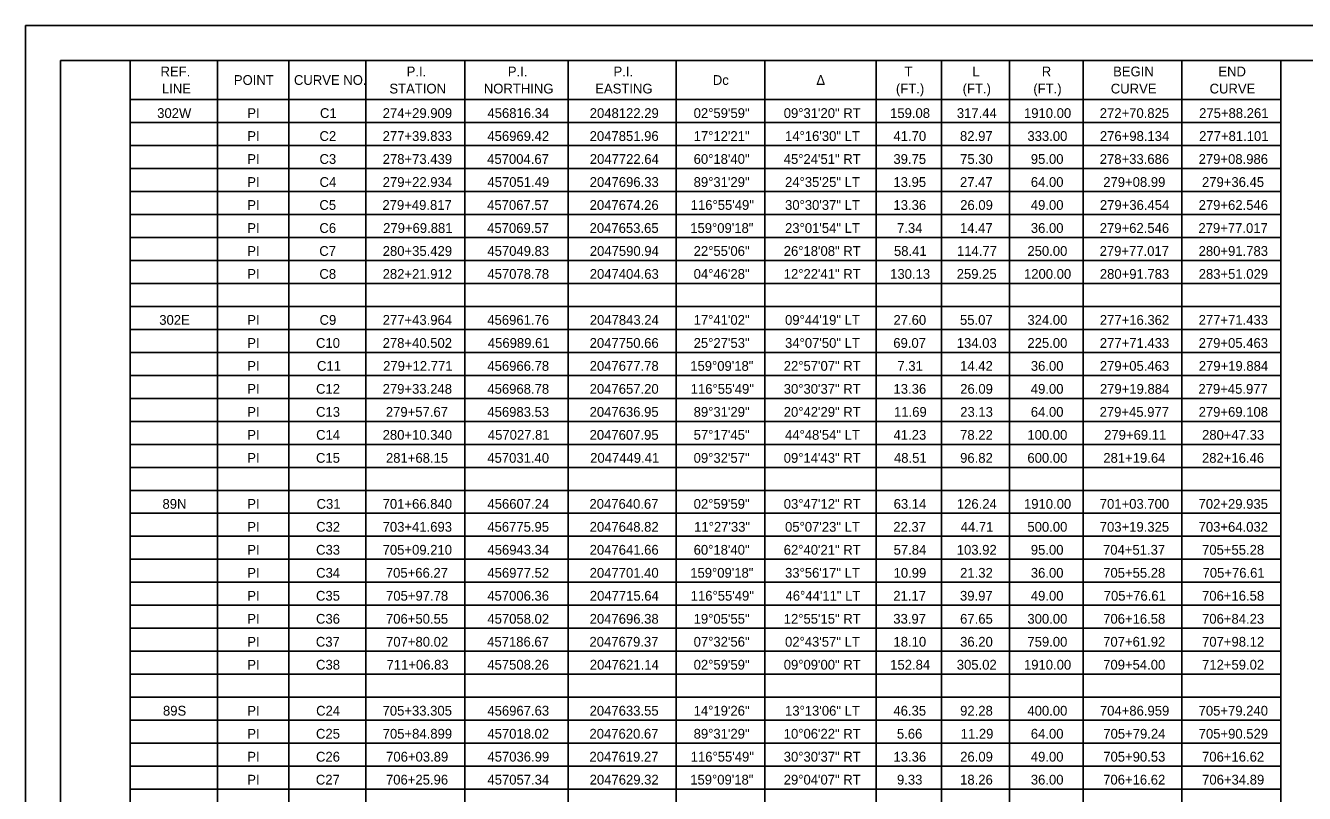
# Model space of a CAD drawing. Extents: x 0 to 34, y 0 to 22.
# Drawn here: x 0 to 18.33, y 11 to 22 of the extents above; entities that cross this region are included whole.
import ezdxf

# ---------------------------------------------------------------- set-up
doc = ezdxf.new("R2010")
doc.units = 0
for name, color, linetype in [('Default', 7, 'Continuous'), ('SH_Border', 7, 'Continuous'), ('SH_Cut_Line', 7, 'Continuous')]:
    doc.layers.add(name, color=color, linetype=linetype)

msp = doc.modelspace()

# ---------------------------------------------------------------- linework, layer by layer
at = {"layer": 'Default'}
for p, q in [((1.5, 21.5), (17.987, 21.5)), ((1.5, 21.5), (1.5, 3.152)), ((2.752, 21.5), (2.752, 3.152)), ((3.773, 21.5), (3.773, 3.152)), ((4.876, 21.5), (4.876, 3.152)), ((6.293, 21.5), (6.293, 3.152)), ((7.775, 21.5), (7.775, 3.152)), ((9.324, 21.5), (9.324, 3.152)), ((10.592, 21.5), (10.592, 3.152)), ((12.189, 21.5), (12.189, 3.152)), ((13.128, 21.5), (13.128, 3.152)), ((14.1, 21.5), (14.1, 3.152)), ((15.154, 21.5), (15.154, 3.152)), ((16.571, 21.5), (16.571, 3.152)), ((17.987, 21.5), (17.987, 3.152)), ((1.5, 20.94), (17.987, 20.94)), ((1.5, 20.611), (17.987, 20.611)), ((1.5, 20.281), (17.987, 20.281)), ((1.5, 19.952), (17.987, 19.952)), ((1.5, 19.622), (17.987, 19.622)), ((1.5, 19.293), (17.987, 19.293)), ((1.5, 18.964), (17.987, 18.964)), ((1.5, 18.634), (17.987, 18.634)), ((1.5, 18.305), (17.987, 18.305)), ((1.5, 17.975), (17.987, 17.975)), ((1.5, 17.646), (17.987, 17.646)), ((1.5, 17.316), (17.987, 17.316)), ((1.5, 16.987), (17.987, 16.987)), ((1.5, 16.658), (17.987, 16.658)), ((1.5, 16.328), (17.987, 16.328)), ((1.5, 15.999), (17.987, 15.999)), ((1.5, 15.669), (17.987, 15.669)), ((1.5, 15.34), (17.987, 15.34)), ((1.5, 15.011), (17.987, 15.011)), ((1.5, 14.681), (17.987, 14.681)), ((1.5, 14.352), (17.987, 14.352)), ((1.5, 14.022), (17.987, 14.022)), ((1.5, 13.693), (17.987, 13.693)), ((1.5, 13.364), (17.987, 13.364)), ((1.5, 13.034), (17.987, 13.034)), ((1.5, 12.705), (17.987, 12.705)), ((1.5, 12.375), (17.987, 12.375)), ((1.5, 12.046), (17.987, 12.046)), ((1.5, 11.716), (17.987, 11.716)), ((1.5, 11.387), (17.987, 11.387)), ((1.5, 11.058), (17.987, 11.058))]:
    msp.add_line(p, q, dxfattribs=at)
at = {"layer": 'SH_Border'}
for points in [[(0.5, 21.5), (1.5, 21.5), (1.5, 0.5), (0.5, 0.5)], [(1.5, 21.5), (33.5, 21.5), (33.5, 0.5), (1.5, 0.5)]]:
    msp.add_lwpolyline(points, close=True, dxfattribs=at)
at = {"layer": 'SH_Cut_Line'}
msp.add_lwpolyline([(0, 0), (34, 0), (34, 22), (0, 22)], close=True, dxfattribs=at)

# ---------------------------------------------------------------- texts
at = {"layer": 'Default'}
for s, p in [('REF.', (1.934, 21.272)), ('POINT', (2.985, 21.15)), ('CURVE NO.', (3.846, 21.15)), ('P.I. ', (5.461, 21.272)), ('P.I. ', (6.911, 21.272)), ('P.I. ', (8.426, 21.272)), ('Dc', (9.849, 21.15)), ('∆', (11.338, 21.15)), ('T', (12.596, 21.272)), ('L', (13.568, 21.272)), ('R', (14.563, 21.272)), ('BEGIN', (15.586, 21.272)), ('END', (17.094, 21.272)), (' LINE', (1.902, 21.027)), ('STATION', (5.214, 21.027)), ('NORTHING', (6.567, 21.027)), ('EASTING', (8.164, 21.027)), ('(FT.)', (12.473, 21.027)), ('(FT.)', (13.429, 21.027)), ('(FT.)', (14.442, 21.027)), ('CURVE', (15.552, 21.027)), ('CURVE', (16.968, 21.027)), ('302W', (1.886, 20.676)), ('PI', (3.177, 20.676)), ('C1', (4.219, 20.676)), ('274+29.909', (5.118, 20.676)), ('456816.34', (6.619, 20.676)), ('2048122.29', (8.085, 20.676)), ('02°59\'59"', (9.574, 20.676)), ('09°31\'20" RT', (10.865, 20.676)), ('159.08', (12.389, 20.676)), ('317.44', (13.346, 20.676)), ('1910.00', (14.308, 20.676)), ('272+70.825', (15.394, 20.676)), ('275+88.261', (16.818, 20.676)), ('PI', (3.177, 20.347)), ('C2', (4.212, 20.347)), ('277+39.833', (5.117, 20.347)), ('456969.42', (6.618, 20.347)), ('2047851.96', (8.084, 20.347)), ('17°12\'21"', (9.574, 20.347)), ('14°16\'30" LT', (10.884, 20.347)), ('41.70', (12.438, 20.347)), ('82.97', (13.391, 20.347)), ('333.00', (14.357, 20.347)), ('276+98.134', (15.396, 20.347)), ('277+81.101', (16.818, 20.347)), ('PI', (3.177, 20.018)), ('C3', (4.212, 20.018)), ('278+73.439', (5.118, 20.018)), ('457004.67', (6.615, 20.018)), ('2047722.64', (8.086, 20.018)), ('60°18\'40"', (9.574, 20.018)), ('45°24\'51" RT', (10.865, 20.018)), ('39.75', (12.437, 20.018)), ('75.30', (13.393, 20.018)), ('95.00', (14.406, 20.018)), ('278+33.686', (15.394, 20.018)), ('279+08.986', (16.811, 20.018)), ('PI', (3.177, 19.688)), ('C4', (4.213, 19.688)), ('279+22.934', (5.118, 19.688)), ('457051.49', (6.619, 19.688)), ('2047696.33', (8.085, 19.688)), ('89°31\'29"', (9.574, 19.688)), ('24°35\'25" LT', (10.884, 19.688)), ('13.95', (12.437, 19.688)), ('27.47', (13.391, 19.688)), ('64.00', (14.406, 19.688)), ('279+08.99', (15.444, 19.688)), ('279+36.45', (16.859, 19.688)), ('PI', (3.177, 19.359)), ('C5', (4.211, 19.359)), ('279+49.817', (5.114, 19.359)), ('457067.57', (6.615, 19.359)), ('2047674.26', (8.084, 19.359)), ('116°55\'49"', (9.532, 19.359)), ('30°30\'37" LT', (10.884, 19.359)), ('13.36', (12.438, 19.359)), ('26.09', (13.394, 19.359)), ('49.00', (14.406, 19.359)), ('279+36.454', (15.396, 19.359)), ('279+62.546', (16.811, 19.359)), ('PI', (3.177, 19.029)), ('C6', (4.211, 19.029)), ('279+69.881', (5.124, 19.029)), ('457069.57', (6.615, 19.029)), ('2047653.65', (8.083, 19.029)), ('159°09\'18"', (9.525, 19.029)), ('23°01\'54" LT', (10.884, 19.029)), ('7.34', (12.489, 19.029)), ('14.47', (13.391, 19.029)), ('36.00', (14.406, 19.029)), ('279+62.546', (15.394, 19.029)), ('279+77.017', (16.808, 19.029)), ('PI', (3.177, 18.7)), ('C7', (4.209, 18.7)), ('280+35.429', (5.118, 18.7)), ('457049.83', (6.618, 18.7)), ('2047590.94', (8.086, 18.7)), ('22°55\'06"', (9.574, 18.7)), ('26°18\'08" RT', (10.865, 18.7)), ('58.41', (12.445, 18.7)), ('114.77', (13.348, 18.7)), ('250.00', (14.357, 18.7)), ('279+77.017', (15.392, 18.7)), ('280+91.783', (16.811, 18.7)), ('PI', (3.177, 18.371)), ('C8', (4.211, 18.371)), ('282+21.912', (5.117, 18.371)), ('457078.78', (6.618, 18.371)), ('2047404.63', (8.085, 18.371)), ('04°46\'28"', (9.574, 18.371)), ('12°22\'41" RT', (10.865, 18.371)), ('130.13', (12.39, 18.371)), ('259.25', (13.344, 18.371)), ('1200.00', (14.308, 18.371)), ('280+91.783', (15.395, 18.371)), ('283+51.029', (16.812, 18.371)), ('302E', (1.916, 17.712)), ('PI', (3.177, 17.712)), ('C9', (4.213, 17.712)), ('277+43.964', (5.118, 17.712)), ('456961.76', (6.617, 17.712)), ('2047843.24', (8.086, 17.712)), ('17°41\'02"', (9.574, 17.712)), ('09°44\'19" LT', (10.884, 17.712)), ('27.60', (12.438, 17.712)), ('55.07', (13.391, 17.712)), ('324.00', (14.357, 17.712)), ('277+16.362', (15.395, 17.712)), ('277+71.433', (16.811, 17.712)), ('PI', (3.177, 17.382)), ('C10', (4.162, 17.382)), ('278+40.502', (5.117, 17.382)), ('456989.61', (6.625, 17.382)), ('2047750.66', (8.084, 17.382)), ('25°27\'53"', (9.574, 17.382)), ('34°07\'50" LT', (10.884, 17.382)), ('69.07', (12.435, 17.382)), ('134.03', (13.345, 17.382)), ('225.00', (14.357, 17.382)), ('277+71.433', (15.395, 17.382)), ('279+05.463', (16.811, 17.382)), ('PI', (3.177, 17.053)), ('C11', (4.177, 17.053)), ('279+12.771', (5.124, 17.053)), ('456966.78', (6.618, 17.053)), ('2047677.78', (8.084, 17.053)), ('159°09\'18"', (9.525, 17.053)), ('22°57\'07" RT', (10.865, 17.053)), ('7.31', (12.494, 17.053)), ('14.42', (13.393, 17.053)), ('36.00', (14.406, 17.053)), ('279+05.463', (15.395, 17.053)), ('279+19.884', (16.813, 17.053)), ('PI', (3.177, 16.724)), ('C12', (4.163, 16.724)), ('279+33.248', (5.117, 16.724)), ('456968.78', (6.618, 16.724)), ('2047657.20', (8.084, 16.724)), ('116°55\'49"', (9.532, 16.724)), ('30°30\'37" RT', (10.865, 16.724)), ('13.36', (12.438, 16.724)), ('26.09', (13.394, 16.724)), ('49.00', (14.406, 16.724)), ('279+19.884', (15.396, 16.724)), ('279+45.977', (16.808, 16.724)), ('PI', (3.177, 16.394)), ('C13', (4.163, 16.394)), ('279+57.67', (5.163, 16.394)), ('456983.53', (6.618, 16.394)), ('2047636.95', (8.083, 16.394)), ('89°31\'29"', (9.574, 16.394)), ('20°42\'29" RT', (10.865, 16.394)), ('11.69', (12.446, 16.394)), ('23.13', (13.394, 16.394)), ('64.00', (14.406, 16.394)), ('279+45.977', (15.392, 16.394)), ('279+69.108', (16.811, 16.394)), ('PI', (3.177, 16.065)), ('C14', (4.164, 16.065)), ('280+10.340', (5.117, 16.065)), ('457027.81', (6.625, 16.065)), ('2047607.95', (8.083, 16.065)), ('57°17\'45"', (9.574, 16.065)), ('44°48\'54" LT', (10.884, 16.065)), ('41.23', (12.439, 16.065)), ('78.22', (13.393, 16.065)), ('100.00', (14.357, 16.065)), ('279+69.11', (15.457, 16.065)), ('280+47.33', (16.86, 16.065)), ('PI', (3.177, 15.735)), ('C15', (4.162, 15.735)), ('281+68.15', (5.165, 15.735)), ('457031.40', (6.617, 15.735)), ('2047449.41', (8.091, 15.735)), ('09°32\'57"', (9.574, 15.735)), ('09°14\'43" RT', (10.865, 15.735)), ('48.51', (12.445, 15.735)), ('96.82', (13.393, 15.735)), ('600.00', (14.357, 15.735)), ('281+19.64', (15.445, 15.735)), ('282+16.46', (16.859, 15.735)), ('89N', (1.962, 15.076)), ('PI', (3.177, 15.076)), ('C31', (4.17, 15.076)), ('701+66.840', (5.117, 15.076)), ('456607.24', (6.619, 15.076)), ('2047640.67', (8.081, 15.076)), ('02°59\'59"', (9.574, 15.076)), ('03°47\'12" RT', (10.865, 15.076)), ('63.14', (12.44, 15.076)), ('126.24', (13.346, 15.076)), ('1910.00', (14.308, 15.076)), ('701+03.700', (15.394, 15.076)), ('702+29.935', (16.81, 15.076)), ('PI', (3.177, 14.747)), ('C32', (4.163, 14.747)), ('703+41.693', (5.117, 14.747)), ('456775.95', (6.617, 14.747)), ('2047648.82', (8.084, 14.747)), ('11°27\'33"', (9.581, 14.747)), ('05°07\'23" LT', (10.884, 14.747)), ('22.37', (12.435, 14.747)), ('44.71', (13.401, 14.747)), ('500.00', (14.357, 14.747)), ('703+19.325', (15.394, 14.747)), ('703+64.032', (16.811, 14.747)), ('PI', (3.177, 14.418)), ('C33', (4.163, 14.418)), ('705+09.210', (5.117, 14.418)), ('456943.34', (6.619, 14.418)), ('2047641.66', (8.084, 14.418)), ('60°18\'40"', (9.574, 14.418)), ('62°40\'21" RT', (10.865, 14.418)), ('57.84', (12.44, 14.418)), ('103.92', (13.345, 14.418)), ('95.00', (14.406, 14.418)), ('704+51.37', (15.441, 14.418)), ('705+55.28', (16.86, 14.418)), ('PI', (3.177, 14.088)), ('C34', (4.164, 14.088)), ('705+66.27', (5.163, 14.088)), ('456977.52', (6.618, 14.088)), ('2047701.40', (8.084, 14.088)), ('159°09\'18"', (9.525, 14.088)), ('33°56\'17" LT', (10.884, 14.088)), ('10.99', (12.439, 14.088)), ('21.32', (13.393, 14.088)), ('36.00', (14.406, 14.088)), ('705+55.28', (15.443, 14.088)), ('705+76.61', (16.867, 14.088)), ('PI', (3.177, 13.759)), ('C35', (4.162, 13.759)), ('705+97.78', (5.166, 13.759)), ('457006.36', (6.617, 13.759)), ('2047715.64', (8.086, 13.759)), ('116°55\'49"', (9.532, 13.759)), ('46°44\'11" LT', (10.891, 13.759)), ('21.17', (12.435, 13.759)), ('39.97', (13.391, 13.759)), ('49.00', (14.406, 13.759)), ('705+76.61', (15.451, 13.759)), ('706+16.58', (16.86, 13.759)), ('PI', (3.177, 13.429)), ('C36', (4.162, 13.429)), ('706+50.55', (5.165, 13.429)), ('457058.02', (6.618, 13.429)), ('2047696.38', (8.084, 13.429)), ('19°05\'55"', (9.574, 13.429)), ('12°55\'15" RT', (10.865, 13.429)), ('33.97', (12.435, 13.429)), ('67.65', (13.393, 13.429)), ('300.00', (14.357, 13.429)), ('706+16.58', (15.443, 13.429)), ('706+84.23', (16.86, 13.429)), ('PI', (3.177, 13.1)), ('C37', (4.16, 13.1)), ('707+80.02', (5.166, 13.1)), ('457186.67', (6.615, 13.1)), ('2047679.37', (8.081, 13.1)), ('07°32\'56"', (9.574, 13.1)), ('02°43\'57" LT', (10.884, 13.1)), ('18.10', (12.438, 13.1)), ('36.20', (13.393, 13.1)), ('759.00', (14.357, 13.1)), ('707+61.92', (15.443, 13.1)), ('707+98.12', (16.86, 13.1)), ('PI', (3.177, 12.771)), ('C38', (4.163, 12.771)), ('711+06.83', (5.173, 12.771)), ('457508.26', (6.617, 12.771)), ('2047621.14', (8.086, 12.771)), ('02°59\'59"', (9.574, 12.771)), ('09°09\'00" RT', (10.865, 12.771)), ('152.84', (12.391, 12.771)), ('305.02', (13.345, 12.771)), ('1910.00', (14.308, 12.771)), ('709+54.00', (15.443, 12.771)), ('712+59.02', (16.86, 12.771)), ('89S', (1.969, 12.112)), ('PI', (3.177, 12.112)), ('C24', (4.164, 12.112)), ('705+33.305', (5.116, 12.112)), ('456967.63', (6.618, 12.112)), ('2047633.55', (8.083, 12.112)), ('14°19\'26"', (9.574, 12.112)), ('13°13\'06" LT', (10.884, 12.112)), ('46.35', (12.437, 12.112)), ('92.28', (13.393, 12.112)), ('400.00', (14.357, 12.112)), ('704+86.959', (15.396, 12.112)), ('705+79.240', (16.811, 12.112)), ('PI', (3.177, 11.782)), ('C25', (4.162, 11.782)), ('705+84.899', (5.118, 11.782)), ('457018.02', (6.618, 11.782)), ('2047620.67', (8.081, 11.782)), ('89°31\'29"', (9.574, 11.782)), ('10°06\'22" RT', (10.865, 11.782)), ('5.66', (12.487, 11.782)), ('11.29', (13.401, 11.782)), ('64.00', (14.406, 11.782)), ('705+79.24', (15.445, 11.782)), ('705+90.529', (16.812, 11.782)), ('PI', (3.177, 11.453)), ('C26', (4.162, 11.453)), ('706+03.89', (5.167, 11.453)), ('457036.99', (6.619, 11.453)), ('2047619.27', (8.081, 11.453)), ('116°55\'49"', (9.532, 11.453)), ('30°30\'37" RT', (10.865, 11.453)), ('13.36', (12.438, 11.453)), ('26.09', (13.394, 11.453)), ('49.00', (14.406, 11.453)), ('705+90.53', (15.444, 11.453)), ('706+16.62', (16.86, 11.453)), ('PI', (3.177, 11.124)), ('C27', (4.16, 11.124)), ('706+25.96', (5.165, 11.124)), ('457057.34', (6.619, 11.124)), ('2047629.32', (8.084, 11.124)), ('159°09\'18"', (9.525, 11.124)), ('29°04\'07" RT', (10.865, 11.124)), ('9.33', (12.488, 11.124)), ('18.26', (13.393, 11.124)), ('36.00', (14.406, 11.124)), ('706+16.62', (15.443, 11.124)), ('706+34.89', (16.861, 11.124))]:
    msp.add_text(s, height=0.14, dxfattribs=at).set_placement(p)

doc.saveas('drawing.dxf')
